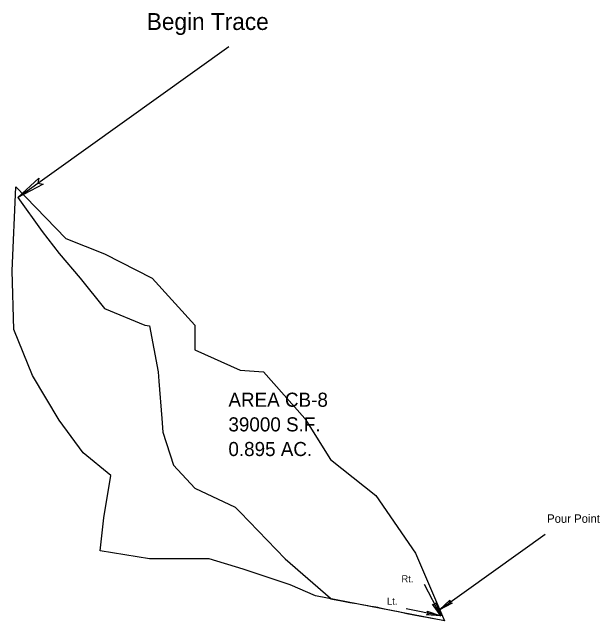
# Model space of a CAD drawing. Extents: x 3199 to 5445, y 3121 to 3553.
import ezdxf

# ---------------------------------------------------------------- set-up
doc = ezdxf.new("R2010")
doc.units = 0
for name, color, linetype in [('Default', 7, 'Continuous'), ('DESIGN - SCRATCH - User 1', 7, 'Continuous'), ('SURVEY - CENTERLINE - Preliminary', 7, 'Continuous'), ('SURVEY - CENTERLINE - Preliminary Text', 7, 'Continuous'), ('SURVEY - CONTROL with Text', 7, 'Continuous'), ('SURVEY - DRAINAGE - Area Shapes', 7, 'Continuous')]:
    doc.layers.add(name, color=color, linetype=linetype)

msp = doc.modelspace()

# ---------------------------------------------------------------- linework, layer by layer
at = {"layer": 'DESIGN - SCRATCH - User 1'}
msp.add_line((3502.22, 3128.41), (3577.11, 3182.08), dxfattribs=at)
msp.add_lwpolyline([(3502.22, 3128.41), (3509.66, 3135.28), (3509.33, 3133.51), (3511.15, 3133.21)], close=True, dxfattribs=at)
msp.add_lwpolyline([(3502.22, 3128.41), (3509.66, 3135.28), (3509.33, 3133.51), (3511.15, 3133.21), (3502.22, 3128.41)], dxfattribs=at)
at = {"layer": 'SURVEY - CENTERLINE - Preliminary'}
msp.add_lwpolyline([(3203.06, 3421.03), (3220.31, 3396.94), (3232.39, 3381.45), (3247.2, 3363.76), (3264.47, 3342.37), (3293.1, 3330.57), (3296.54, 3330.13), (3302.7, 3297.38), (3302.99, 3290.71), (3305.19, 3264.19), (3305.92, 3254.49), (3313.5, 3231.01), (3328.62, 3214.65), (3357.34, 3201.29), (3360.7, 3197.82), (3392.78, 3164.63), (3424.85, 3136.56), (3424.85, 3136.56), (3424.85, 3136.51), (3424.84, 3136.46), (3424.84, 3136.38), (3424.84, 3136.33), (3424.83, 3136.25), (3424.83, 3136.21), (3428.86, 3135.42), (3433.79, 3134.55), (3438.71, 3133.68), (3443.63, 3132.81), (3448.56, 3131.94), (3451.42, 3131.44), (3453.48, 3131.08), (3455.31, 3130.74), (3456.93, 3130.43), (3458.13, 3130.2), (3458.4, 3130.15), (3459.29, 3129.97), (3463.29, 3129.13), (3468.19, 3128.11), (3473.08, 3127.09), (3479.11, 3125.89), (3489.01, 3123.91), (3493.21, 3123.08), (3498.02, 3122.12)], dxfattribs=at)
at = {"layer": 'SURVEY - CENTERLINE - Preliminary Text'}
msp.add_line((3203.06, 3421.03), (3352.82, 3528.37), dxfattribs=at)
msp.add_lwpolyline([(3203.06, 3421.03), (3217.94, 3434.77), (3217.28, 3431.22), (3220.91, 3430.62)], close=True, dxfattribs=at)
msp.add_lwpolyline([(3203.06, 3421.03), (3217.94, 3434.77), (3217.28, 3431.22), (3220.91, 3430.62), (3203.06, 3421.03)], dxfattribs=at)
at = {"layer": 'SURVEY - CONTROL with Text'}
for q in [(3491.5, 3146.3), (3478.57, 3129.16)]:
    msp.add_line((3503.06, 3124.13), q, dxfattribs=at)
for points in [[(3503.06, 3124.13), (3497.3, 3132.46), (3499.01, 3131.89), (3499.57, 3133.64)], [(3503.06, 3124.13), (3492.97, 3124.93), (3494.49, 3125.89), (3493.48, 3127.43)]]:
    msp.add_lwpolyline(points, close=True, dxfattribs=at)
for points in [[(3503.06, 3124.13), (3497.3, 3132.46), (3499.01, 3131.89), (3499.57, 3133.64), (3503.06, 3124.13)], [(3503.06, 3124.13), (3492.97, 3124.93), (3494.49, 3125.89), (3493.48, 3127.43), (3503.06, 3124.13)]]:
    msp.add_lwpolyline(points, dxfattribs=at)
at = {"layer": 'SURVEY - DRAINAGE - Area Shapes'}
for points in [[(3261.32, 3170.23), (3264.09, 3193.79), (3268.94, 3223.87), (3249.26, 3239.87), (3232.23, 3262.94), (3213.44, 3294.67), (3200.17, 3327.4), (3199, 3369.1), (3201.64, 3428.76)], [(3201.64, 3428.76), (3237.13, 3392.04), (3264.47, 3381.17), (3298.37, 3363.76), (3328.62, 3330.57), (3328.62, 3313.01), (3360.7, 3298.51), (3377.22, 3297.38), (3406.63, 3264.19), (3424.85, 3235.05), (3456.93, 3209.58), (3485.21, 3168.56), (3505.66, 3120.58)], [(3505.66, 3120.58), (3414.14, 3138.29), (3396.32, 3146.17), (3363.01, 3157.35), (3338.84, 3164.63), (3296.54, 3164.63), (3261.32, 3170.23)]]:
    msp.add_lwpolyline(points, dxfattribs=at)

# ---------------------------------------------------------------- texts
at = {"layer": 'Default'}
for s, p in [('AREA CB-8', (3352.43, 3272.56)), ('39000 S.F.', (3352.43, 3255.06)), ('0.895 AC.', (3352.43, 3237.56))]:
    msp.add_text(s, height=10, dxfattribs=at).set_placement(p)
at = {"layer": 'DESIGN - SCRATCH - User 1'}
msp.add_text('Pour Point', height=6, dxfattribs=at).set_placement((3578.58, 3190.16))
at = {"layer": 'SURVEY - CENTERLINE - Preliminary Text'}
msp.add_text('Begin Trace', height=12, dxfattribs=at).set_placement((3294.52, 3540.07))
at = {"layer": 'SURVEY - CONTROL with Text'}
for s, p in [(' Rt.', (3473.34, 3147.94)), ('Lt.', (3464.96, 3132.08))]:
    msp.add_text(s, height=5, dxfattribs=at).set_placement(p)

doc.saveas('drawing.dxf')
